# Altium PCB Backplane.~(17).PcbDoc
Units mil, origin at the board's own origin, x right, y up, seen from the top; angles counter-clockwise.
Board outline 6520 x 1500 mil, 6 copper layers (Top Layer, DGND, +5V, AGND, VCC, Bottom Layer), stack 50.76 mil thick; 22 components, 84 nets, 235 pads, 4 vias.
Unrouted connection lines stored in the file: 38.
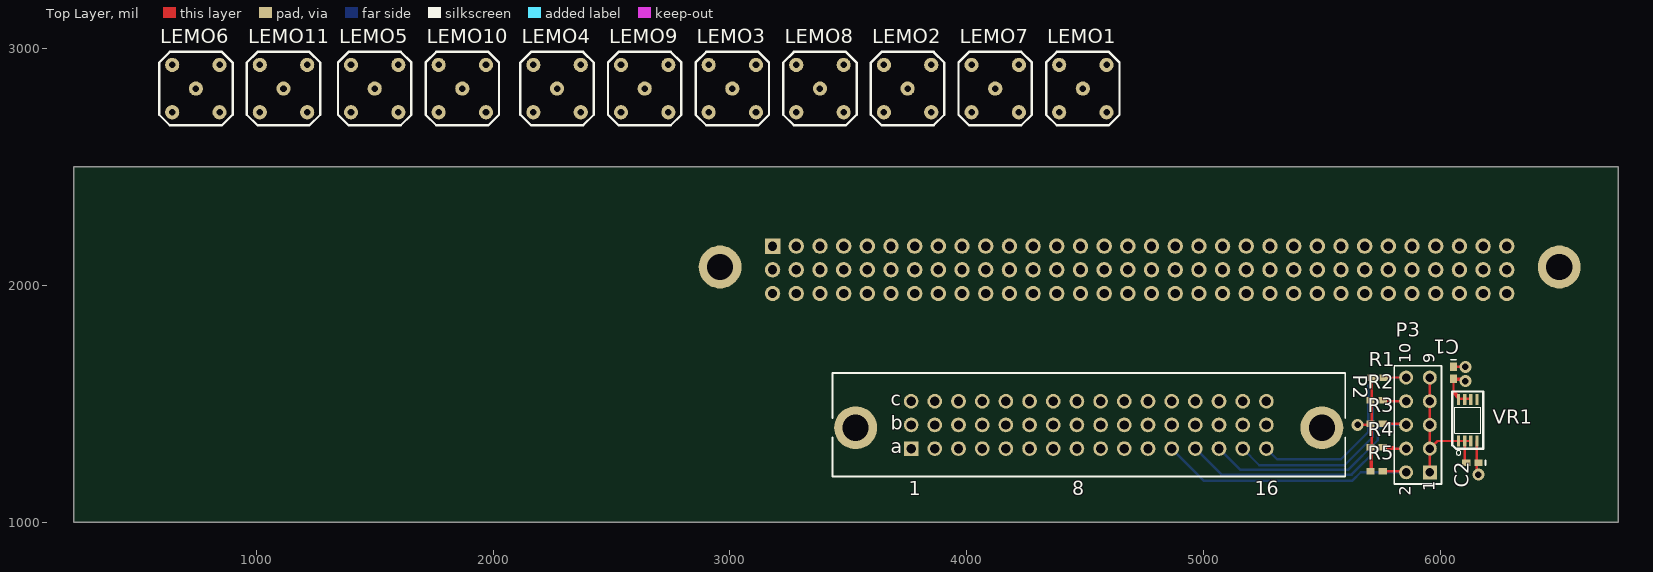
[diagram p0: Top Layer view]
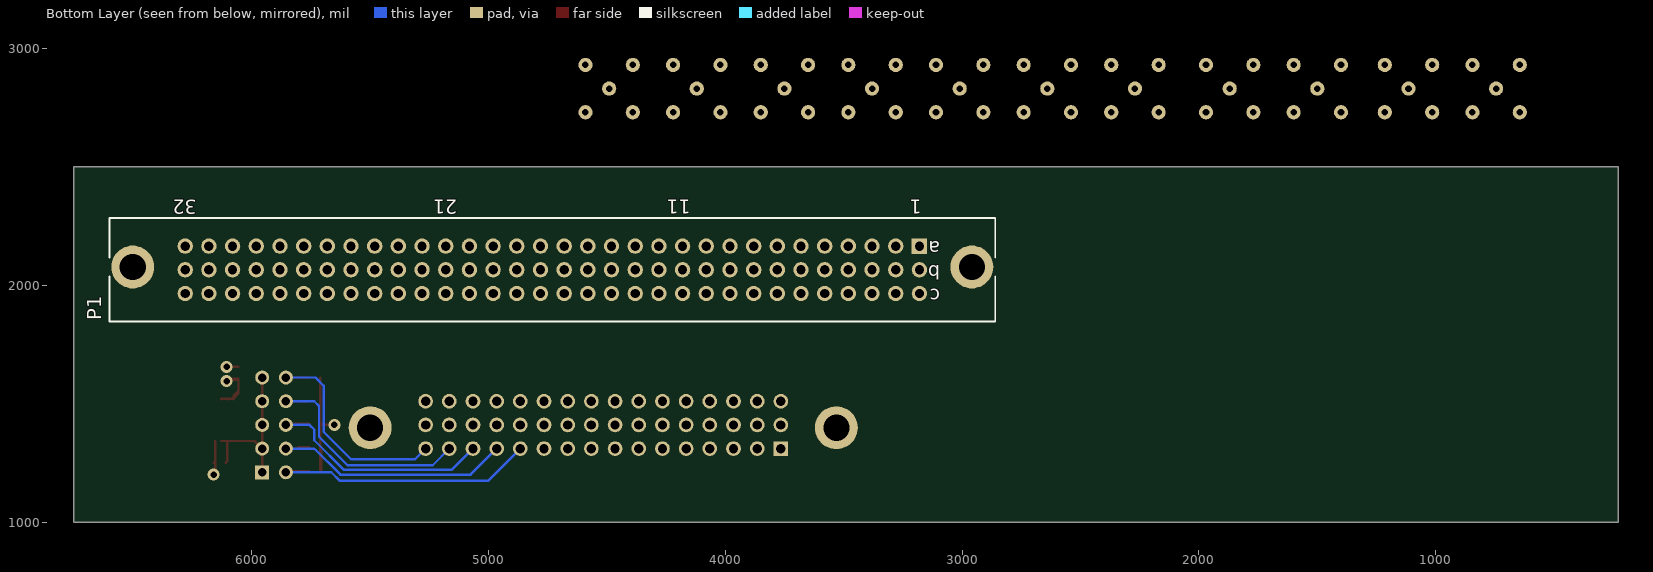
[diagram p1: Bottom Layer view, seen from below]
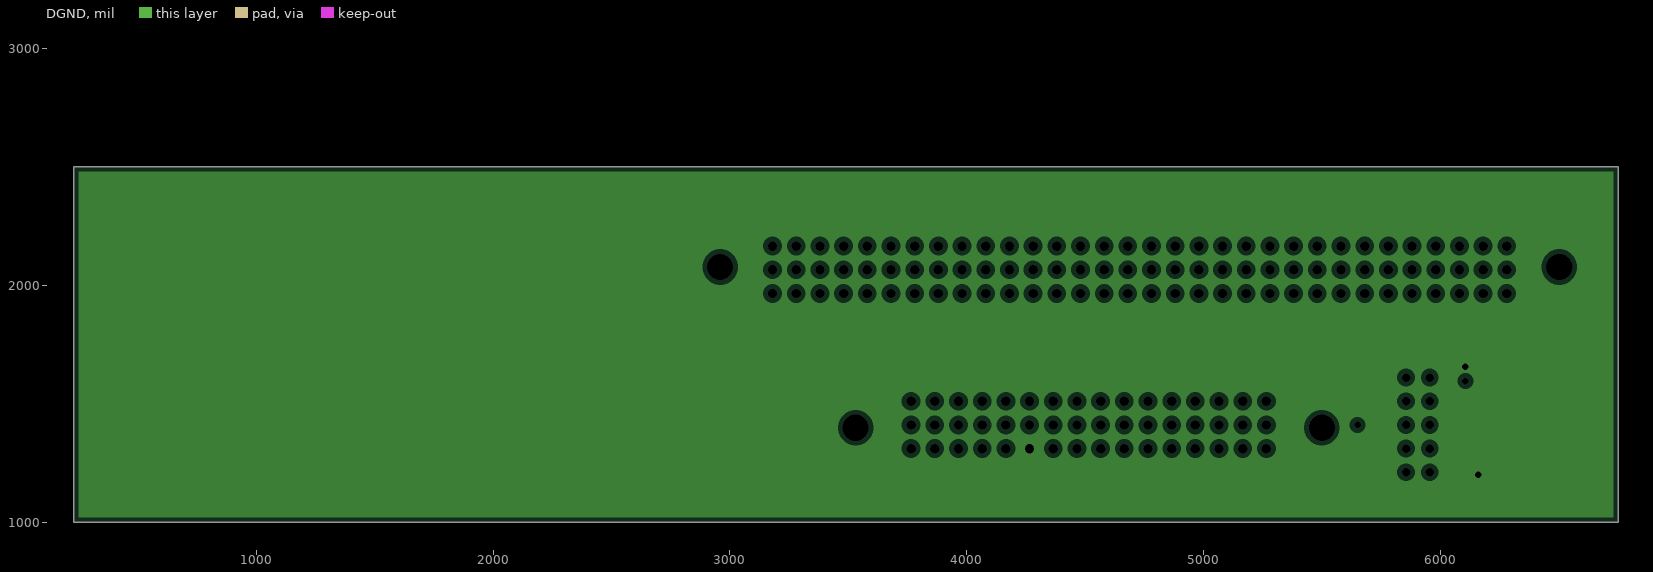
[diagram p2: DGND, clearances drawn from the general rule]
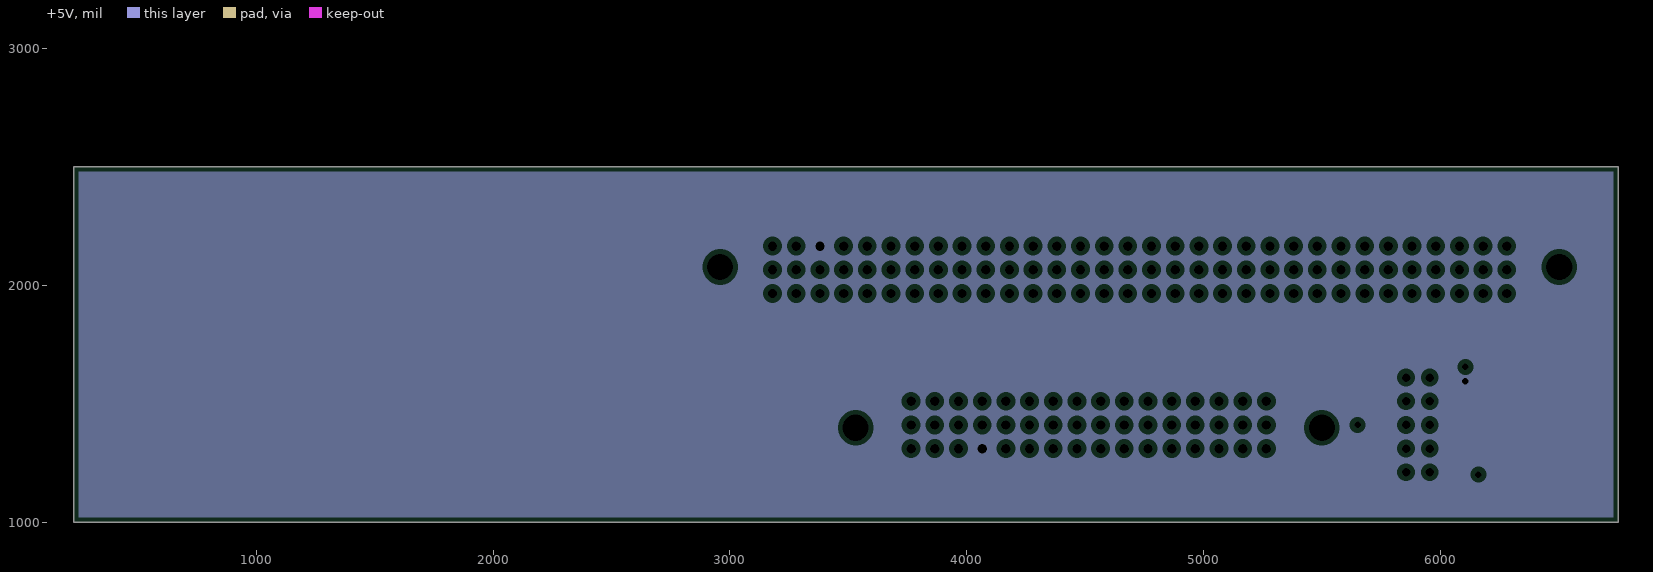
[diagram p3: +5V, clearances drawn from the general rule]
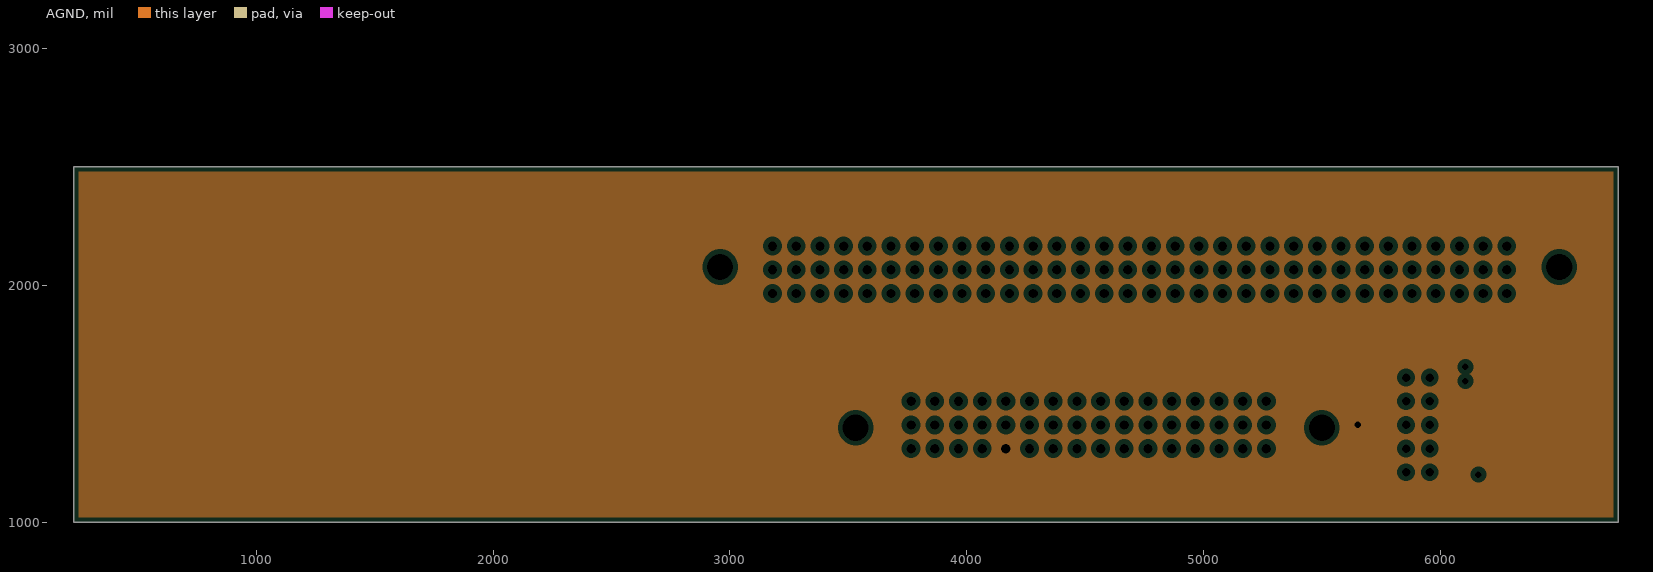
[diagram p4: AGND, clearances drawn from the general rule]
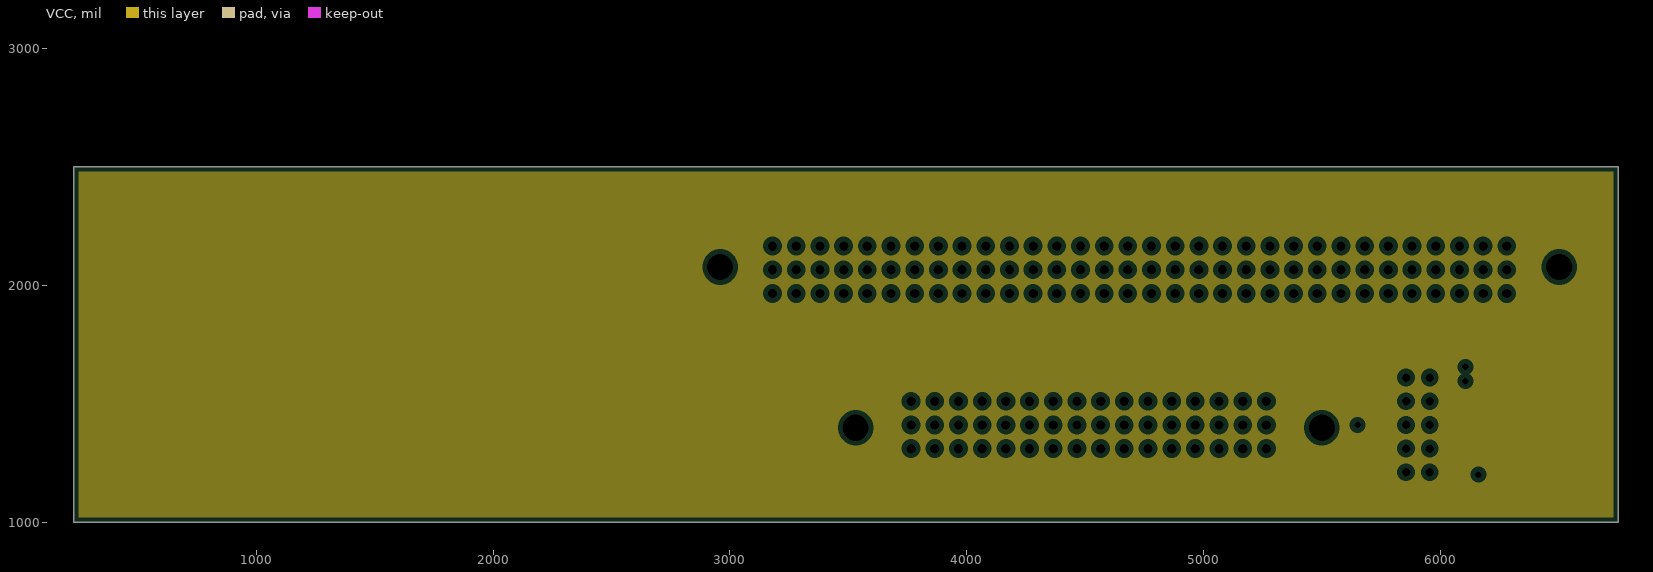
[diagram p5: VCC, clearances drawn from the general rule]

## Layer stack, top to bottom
Top Layer: signal copper 1.4
Dielectric: prepreg 5.1, FR-4, Dk 4.8
DGND: plane copper 1.4, net DGND
Dielectric: core 10.72, FR-4, Dk 4.8
+5V: plane copper 1.4, net +5V
Dielectric: prepreg 10.72, FR-4, Dk 4.8
AGND: plane copper 1.4, net AGND
Dielectric: core 10.72, FR-4, Dk 4.8
VCC: plane copper 1.4
Dielectric: prepreg 5.1, FR-4, Dk 4.8
Bottom Layer: signal copper 1.4

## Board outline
230,1000 6750,1000 6750,2500 230,2500

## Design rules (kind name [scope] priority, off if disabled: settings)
Clearance [All] p1: gap=10
ComponentClearance [All] p1: gap=10 collisioncheckmode=3 verticalgap=10
PlaneClearance [All] p1: clearance=20
PlaneConnect [All] p1: planeconnectstyle=Relief reliefexpansion=20 reliefentries=4 reliefconductorwidth=10 reliefairgap=10
PolygonConnect [All] p1: connectstyle=Relief reliefconductorwidth=10 reliefentries=4 polygonreliefangle="90 Angle"
RoomDefinition LEMO [InComponentClass('LEMO')] p1: confinementstyle=ConfineIn formatcopy=TRUE lockcomponents=FALSE outline 580,2665 4655,2665 4655,3100 580,3100
RoomDefinition "Digital Connector" [InComponentClass('Digital Connector')] p2: confinementstyle=ConfineIn formatcopy=TRUE lockcomponents=FALSE outline 3170,1085 6595,1085 6595,1895 3170,1895
RoomDefinition "Analog Connector" [InComponentClass('Analog Connector')] p3: confinementstyle=ConfineIn formatcopy=TRUE lockcomponents=FALSE outline 2650,1745 6670,1745 6670,2420 2650,2420
RoutingVias [All] p1: holewidth=28 width=50 viastyle="Through Hole" minholewidth=28 minwidth=50 maxholewidth=28 maxwidth=50
SolderMaskExpansion [All] p1: expansion=4
SupplyNets VCC [OnLayer('VCC')] p1: voltage=10.00
SupplyNets +5V [OnLayer('+5V')] p2: voltage=5.000
SupplyNets DGND [OnLayer(DGND)] p3: voltage=0.000
SupplyNets AGND [OnLayer('AGND')] p4: voltage=0.000
TestPointUsage [All] p1: valid=0 allowmultiple=FALSE
Testpoint [All] p1: side=15 testpointundercomponent=TRUE minsize=40 maxsize=100 preferedsize=60 minholesize=0 maxholesize=40 preferedholesize=32 testpointgrid=1 style=1023 order=0123456789
Width Width_BIAS [InNetClass('BIAS')] p1: maxlimit=10 minlimit=4 preferedwidth=5
Width [All] p2: maxlimit=7.35 minlimit=2.1 preferedwidth=7.35 impedancedriven=TRUE minimp=50.000000 maximp=80.000000 favimp=50.000000
16 further rules are at their usual default settings.

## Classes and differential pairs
net class BIAS: SIPMBIAS1 SIPMBIAS2 SIPMBIAS3 SIPMBIAS4 SIPMBIAS5 SIPMBIAS6 SIPMBIAS7 SIPMBIAS8 SIPMBIAS9 SIPMBIAS10 SIPMBIAS11 SIPMBIAS12 SIPMBIAS13 SIPMBIAS14 SIPMBIAS15 SIPMBIAS16 SIPMBIAS17 SIPMBIAS18 SIPMBIAS19 SIPMBIAS20 SIPMBIAS21 SIPMBIAS22 SIPMBIAS23 SIPMBIAS24 SIPMBIAS25 SIPMBIAS26 SIPMBIAS27 SIPMBIAS28 SIPMBIAS29 SIPMBIAS30 SIPMBIAS31 SIPMBIAS32
component class LEMO: LEMO1 LEMO2 LEMO3 LEMO4 LEMO5 LEMO6 LEMO7 LEMO8 LEMO9 LEMO10 LEMO11
component class "Digital Connector": C1 C2 P2 P3 R1 R2 R3 R4 R5 R? VR1
component class "Analog Connector": P1

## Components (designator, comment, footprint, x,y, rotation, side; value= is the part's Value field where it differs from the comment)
C1 "Kemet C0402C104K8PACTU" 0402 6055,1630 r270 top
C2 "Kemet C1206C106K9PACTU" 0402 6135,1250 r180 top
LEMO1 "LEMO EPA.00" "LEMO EPA.00" 4490,2830 r0 top
LEMO2 "LEMO EPA.00" "LEMO EPA.00" 3750,2830 r0 top
LEMO3 "LEMO EPA.00" "LEMO EPA.00" 3010,2830 r0 top
LEMO4 "LEMO EPA.00" "LEMO EPA.00" 2270,2830 r0 top
LEMO5 "LEMO EPA.00" "LEMO EPA.00" 1500,2830 r0 top
LEMO6 "LEMO EPA.00" "LEMO EPA.00" 745,2830 r0 top
LEMO7 "LEMO EPA.00" "LEMO EPA.00" 4120,2830 r0 top
LEMO8 "LEMO EPA.00" "LEMO EPA.00" 3380,2830 r0 top
LEMO9 "LEMO EPA.00" "LEMO EPA.00" 2640,2830 r0 top
LEMO10 "LEMO EPA.00" "LEMO EPA.00" 1870,2830 r0 top
LEMO11 "LEMO EPA.00" "LEMO EPA.00" 1115,2830 r0 top
P1 "DIN41612 96 pin, Backplane" EURO2.54-2V96 4730,2065 r0 bottom
P2 "DIN41612 48 pin, Backplane" EURO2.54-2V48 4515,1410 r0 top
P3 "Header 5X2" HDR2X5 5955,1210 r90 top
R1 "Res2" 1005[0402] 5735,1610 r0 top
R2 "Res2" 1005[0402] 5730,1515 r0 top
R3 "Res2" 1005[0402] 5730,1415 r0 top
R4 "Res2" 1005[0402] 5730,1315 r0 top
R5 "Res2" 1005[0402] 5730,1215 r0 top
VR1 "" RM-8 6115,1430 r0 top

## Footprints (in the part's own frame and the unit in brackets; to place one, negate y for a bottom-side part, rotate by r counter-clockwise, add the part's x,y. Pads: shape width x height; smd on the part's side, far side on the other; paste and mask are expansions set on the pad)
0402 [mm] "Chip Capacitor; Body 1.0 x 0.5 mm (LxW typ)"
  rect 0.9x0.7 smd: 1(-0.65,0) 2(0.65,0)
  silkscreen extent -1.4,-0.25 -1.4,0.25
1005[0402] [mm] "Chip Resistor; Body 1.1 x 0.5 mm (LxW typ)"
  rect 0.9x0.7 smd: 1(-0.65,0) 2(0.65,0)
EURO2.54-2V48 [mil] "Connector; DIN 41612, Type 2C, Thru-Hole; Rows a+b+c, 48 Position; Vertical"
  round 181.1 hole 110.24: 17(-984.25,-11.81) 18(984.25,-11.81)
  rect 62x62 hole 39.37: A1(-750,-100)
  round 62 hole 39.37: A2(-650,-100) A3(-550,-100) A4(-450,-100) A5(-350,-100) A6(-250,-100) A7(-150,-100) A8(-50,-100) A9(50,-100) A10(150,-100) A11(250,-100) A12(350,-100) A13(450,-100) A14(550,-100) A15(650,-100) A16(750,-100) B1(-750,0) B2(-650,0) B3(-550,0) B4(-450,0) B5(-350,0) B6(-250,0) B7(-150,0) B8(-50,0) B9(50,0) B10(150,0) B11(250,0) B12(350,0) B13(450,0) B14(550,0) B15(650,0) B16(750,0) C1(-750,100) C2(-650,100) C3(-550,100) C4(-450,100) C5(-350,100) C6(-250,100) C7(-150,100) C8(-50,100) C9(50,100) C10(150,100) C11(250,100) C12(350,100) C13(450,100) C14(550,100) C15(650,100) C16(750,100)
  silkscreen extent -1083,-219 1083,219
EURO2.54-2V96 [mm] "Connector; DIN 41612, Type C, Thru-Hole; Rows a+b+c, 96 Position; Vertical"
  round 4.6 hole 2.8: 33(-45,-0.3) 34(45,-0.3)
  rect 1.65x1.65 hole 1: A1(-39.37,-2.54)
  round 1.65 hole 1: A2(-36.83,-2.54) A3(-34.29,-2.54) A4(-31.75,-2.54) A5(-29.21,-2.54) A6(-26.67,-2.54) A7(-24.13,-2.54) A8(-21.59,-2.54) A9(-19.05,-2.54) A10(-16.51,-2.54) A11(-13.97,-2.54) A12(-11.43,-2.54) A13(-8.89,-2.54) A14(-6.35,-2.54) A15(-3.81,-2.54) A16(-1.27,-2.54) A17(1.27,-2.54) A18(3.81,-2.54) A19(6.35,-2.54) A20(8.89,-2.54) A21(11.43,-2.54) A22(13.97,-2.54) A23(16.51,-2.54) A24(19.05,-2.54) A25(21.59,-2.54) A26(24.13,-2.54) A27(26.67,-2.54) A28(29.21,-2.54) A29(31.75,-2.54) A30(34.29,-2.54) A31(36.83,-2.54) A32(39.37,-2.54) B1(-39.37,0) B2(-36.83,0) B3(-34.29,0) B4(-31.75,0) B5(-29.21,0) B6(-26.67,0) B7(-24.13,0) B8(-21.59,0) B9(-19.05,0) B10(-16.51,0) B11(-13.97,0) B12(-11.43,0) B13(-8.89,0) B14(-6.35,0) B15(-3.81,0) B16(-1.27,0) B17(1.27,0) B18(3.81,0) B19(6.35,0) B20(8.89,0) B21(11.43,0) B22(13.97,0) B23(16.51,0) B24(19.05,0) B25(21.59,0) B26(24.13,0) B27(26.67,0) B28(29.21,0) B29(31.75,0) B30(34.29,0) B31(36.83,0) B32(39.37,0) C1(-39.37,2.54) C2(-36.83,2.54) C3(-34.29,2.54) C4(-31.75,2.54) C5(-29.21,2.54) C6(-26.67,2.54) C7(-24.13,2.54) C8(-21.59,2.54) C9(-19.05,2.54) C10(-16.51,2.54) C11(-13.97,2.54) C12(-11.43,2.54) C13(-8.89,2.54) C14(-6.35,2.54) C15(-3.81,2.54) C16(-1.27,2.54) C17(1.27,2.54) C18(3.81,2.54) C19(6.35,2.54) C20(8.89,2.54) C21(11.43,2.54) C22(13.97,2.54) C23(16.51,2.54) C24(19.05,2.54) C25(21.59,2.54) C26(24.13,2.54) C27(26.67,2.54) C28(29.21,2.54) C29(31.75,2.54) C30(34.29,2.54) C31(36.83,2.54) C32(39.37,2.54)
  silkscreen extent -47.5,-5.55 47.5,5.55
HDR2X5 [mm] "Connector; Header; 5x2 Position"
  rect 1.5x1.5 hole 0.9: 1(0,0)
  round 1.5 hole 0.9: 2(0,2.54) 3(2.54,0) 4(2.54,2.54) 5(5.08,0) 6(5.08,2.54) 7(7.62,0) 8(7.62,2.54) 9(10.16,0) 10(10.16,2.54)
  silkscreen extent -1.27,-1.27 11.43,3.81
"LEMO EPA.00" [mil]
  round 60 hole 27.56: 0(0,0) 1(-100,100) 2(100,100) 3(100,-100) 4(-100,-100)
  silkscreen extent -155,-155 155,155
RM-8 [mil]
  rect 13.4x46.9 smd: 1(-38.6,-87.8) 2(-12.6,-87.8) 3(12.6,-87.8) 4(38.6,-87.8) 5(38.6,87.8) 6(12.6,87.8) 7(-12.6,87.8) 8(-38.6,87.8)
  silkscreen extent -65,-148 65,121

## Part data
C1 C2: library part Cap, "Capacitor"
P3: "Header, 5-Pin, Dual row"
R1 R2 R3 R4 R5: "Resistor"
VR1: library part ADP3335

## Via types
v1: diameter 50, hole 28, Top Layer to Bottom Layer, 4 vias

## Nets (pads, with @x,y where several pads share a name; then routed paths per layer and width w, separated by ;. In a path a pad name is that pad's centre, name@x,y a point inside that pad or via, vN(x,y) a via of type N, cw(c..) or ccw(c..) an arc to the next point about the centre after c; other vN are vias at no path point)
+3.3V: C2.2 P3.1 P3.3 P3.5 P3.7 P3.9 VR1.1 VR1.2 VR1.3 | length 681
  Top Layer w10: P3.1 P3.3 ; P3.9 P3.7 P3.5 P3.3 ; C2.2 6102.4,1257.01 VR1.2 ; VR1.3 VR1.2 ; P3.3 5987.2,1342.2 VR1.1 VR1.2
+5V: C1.2 P1.A3 P2.A4 VR1.6 VR1.7 VR1.8 | length 470.4
  Top Layer w10: VR1.8 VR1.8@6076.4,1521 ; VR1.7 VR1.7@6102.4,1520 ; v1(6105,1595) v1@6100,1600 ; VR1.6 VR1.6@6127.6,1520 ; 6055,1554.4 C1.2@6055,1600 ; 6055,1554.4 6055,1543.6 VR1.8@6076.4,1522.2 ; 6055,1554.4 6076.4,1533 VR1.8@6076.4,1522.2 ; C1.2@6055,1600 v1@6100,1600 ; C1.2@6055,1600 C1.2 6095.59,1604.41 v1@6100,1600 ; C1.2@6055,1600 v1@6100,1600 ; VR1.8@6076.4,1521 VR1.8@6077.6,1521 ; VR1.8@6076.4,1521 VR1.8@6076.4,1522.2 ; VR1.8@6076.4,1521 VR1.8@6077.6,1521 ; VR1.8@6076.4,1522.2 VR1.8@6077.6,1521 ; VR1.8@6077.6,1521 VR1.8@6078.6,1520 ; VR1.8@6077.6,1521 VR1.7@6102.4,1521 ; VR1.8@6077.6,1521 VR1.7@6102.4,1521 ; VR1.8@6077.6,1521 VR1.8@6078.6,1520 ; VR1.8@6078.6,1520 VR1.7@6102.4,1520 ; VR1.8@6078.6,1520 VR1.7@6102.4,1520 ; v1@6100,1600 v1@6105,1600 ; v1@6100,1600 v1@6105,1600 ; VR1.7@6102.4,1520 VR1.6@6127.6,1520 ; VR1.7@6102.4,1520 VR1.7@6102.4,1521 ; VR1.7@6102.4,1520 VR1.6@6127.6,1520 ; v1@6105,1600 6115,1600 v1@6105,1600
+210V: P2.A2
-5V: P2.A3
ADC_EXT1: P2.A7
ADC_EXT2: P2.A8
AGND: LEMO1.1 LEMO1.2 LEMO1.3 LEMO1.4 LEMO2.1 LEMO2.2 LEMO2.3 LEMO2.4 LEMO3.1 LEMO3.2 LEMO3.3 LEMO3.4 LEMO4.1 LEMO4.2 LEMO4.3 LEMO4.4 LEMO5.1 LEMO5.2 LEMO5.3 LEMO5.4 LEMO6.1 LEMO6.2 LEMO6.3 LEMO6.4 LEMO7.1 LEMO7.2 LEMO7.3 LEMO7.4 LEMO8.1 LEMO8.2 LEMO8.3 LEMO8.4 LEMO9.1 LEMO9.2 LEMO9.3 LEMO9.4 LEMO10.1 LEMO10.2 LEMO10.3 LEMO10.4 LEMO11.1 LEMO11.2 LEMO11.3 LEMO11.4 P2.A5 R1.1 R2.1 R3.1 R4.1 R5.1 | length 1259.6
  Top Layer w10: v1(5650,1410) R3.1@5699.41,1410 ; R5.1 R5.1@5705,1215 ; R4.1 R4.1@5705,1315 ; R2.1 R2.1@5709,1515 ; R3.1@5699.41,1410 R3.1@5699.41,1415 ; R3.1@5699.41,1410 R3.1@5699.41,1415 ; R3.1@5699.41,1415 R3.1 R3.1@5709,1415 ; R5.1@5705,1215 R4.1@5705,1315 ; R5.1@5705,1215 R4.1@5705,1315 ; R4.1@5705,1315 R4.1@5709.41,1315 ; R3.1@5709,1415 R2.1@5709,1515 ; R3.1@5709,1415 R2.1@5709,1515 ; R2.1@5709,1515 R2.1@5709.41,1515 ; R4.1@5709.41,1315 5709.41,1220 R4.1@5709.41,1315 ; R4.1@5709.41,1315 R3.1@5709.41,1415 ; R4.1@5709.41,1315 R3.1@5709.41,1415 ; R3.1@5709.41,1415 R2.1@5709.41,1515 ; R3.1@5709.41,1415 R2.1@5709.41,1515 ; R2.1@5709.41,1515 R1.1 R2.1@5709.41,1515
CP2201/LA: P2.A1
DGND: C1.1 C2.1 P2.A6 VR1.4 | length 337.9
  Top Layer w10: C1.1 6104.41,1655.59 v1(6105,1655) ; v1(6160,1200) v1@6153.6,1206.4 ; C2.1 C2.1@6153.6,1250 ; v1@6153.6,1206.4 C2.1@6153.6,1250 ; v1@6153.6,1206.4 C2.1@6153.6,1250 ; C2.1@6153.6,1250 VR1.4 C2.1@6153.6,1250
ID0: P2.A16 P3.10 R1.2 | length 960.2
  Top Layer w10: R1.2 P3.10
  Bottom Layer w10: P2.A16 5310,1265 5580,1265 5695,1380 5695,1575 5730,1610 P3.10
ID1: P2.A15 P3.8 R2.2 | length 1001.4
  Top Layer w10: R2.2@5760.59,1510 P3.8
  Bottom Layer w10: P2.A15 5235,1240 5595,1240 5715,1360 5715,1490 5735,1510 P3.8
ID2: P2.A14 P3.6 R3.2 | length 1136.2
  Top Layer w10: P3.6 P3.6@5855,1415 ; P3.6@5855,1415 R3.2 P3.6@5855,1415
  Bottom Layer w10: P2.A14 5155,1220 5610,1220 5735,1345 5735,1390 5755,1410 P3.6
ID3: P2.A13 P3.4 R4.2 | length 1129
  Top Layer w10: R4.2 5802,1315 5807,1310 ; R4.2@5760.59,1310 5807,1310 ; P3.4 5807,1310
  Bottom Layer w10: P2.A13 5075,1200 5625,1200 5735,1310 P3.4
ID4: P2.A12 P3.2 R5.2 | length 1264.2
  Top Layer w10: P3.2 P3.2@5855,1215 ; P3.2@5855,1215 R5.2 P3.2@5855,1215
  Bottom Layer w10: P2.A12 5000,1175 5628.28,1175 5663.28,1210 P3.2
SIPMBIAS1: P1.B1 P2.C1
SIPMBIAS2: P1.B2 P2.B1
SIPMBIAS3: P1.B3 P2.C2
SIPMBIAS4: P1.B4 P2.B2
SIPMBIAS5: P1.B5 P2.C3
SIPMBIAS6: P1.B6 P2.B3
SIPMBIAS7: P1.B7 P2.C4
SIPMBIAS8: P1.B8 P2.B4
SIPMBIAS9: P1.B9 P2.C5
SIPMBIAS10: P1.B10 P2.B5
SIPMBIAS11: P1.B11 P2.C6
SIPMBIAS12: P1.B12 P2.B6
SIPMBIAS13: P1.B13 P2.C7
SIPMBIAS14: P1.B14 P2.B7
SIPMBIAS15: P1.B15 P2.C8
SIPMBIAS16: P1.B16 P2.B8
SIPMBIAS17: P1.B17 P2.C9
SIPMBIAS18: P1.B18 P2.B9
SIPMBIAS19: P1.B19 P2.C10
SIPMBIAS20: P1.B20 P2.B10
SIPMBIAS21: P1.B21 P2.C11
SIPMBIAS22: P1.B22 P2.B11
SIPMBIAS23: P1.B23 P2.C12
SIPMBIAS24: P1.B24 P2.B12
SIPMBIAS25: P1.B25 P2.C13
SIPMBIAS26: P1.B26 P2.B13
SIPMBIAS27: P1.B27 P2.C14
SIPMBIAS28: P1.B28 P2.B14
SIPMBIAS29: P1.B29 P2.C15
SIPMBIAS30: P1.B30 P2.B15
SIPMBIAS31: P1.B31 P2.C16
SIPMBIAS32: P1.B32 P2.B16
SIPMOUT1: P1.C1
SIPMOUT2: P1.C2
SIPMOUT3: P1.C3
SIPMOUT4: P1.C4
SIPMOUT5: P1.C5
SIPMOUT6: P1.C6
SIPMOUT7: P1.C7
SIPMOUT8: P1.C8
SIPMOUT9: P1.C9
SIPMOUT10: P1.C10
SIPMOUT11: P1.C11
SIPMOUT12: P1.C12
SIPMOUT13: P1.C13
SIPMOUT14: P1.C14
SIPMOUT15: P1.C15
SIPMOUT16: P1.C16
SIPMOUT17: P1.C17
SIPMOUT18: P1.C18
SIPMOUT19: P1.C19
SIPMOUT20: P1.C20
SIPMOUT21: P1.C21
SIPMOUT22: P1.C22
SIPMOUT23: P1.C23
SIPMOUT24: P1.C24
SIPMOUT25: P1.C25
SIPMOUT26: P1.C26
SIPMOUT27: P1.C27
SIPMOUT28: P1.C28
SIPMOUT29: P1.C29
SIPMOUT30: P1.C30
SIPMOUT31: P1.C31
SIPMOUT32: P1.C32
SUMMED1: LEMO1.0 LEMO6.0 P1.A1
SUMMED2: LEMO2.0 P1.A6
SUMMED3: LEMO3.0 P1.A11
SUMMED4: LEMO4.0 P1.A16
SUMMED5: LEMO5.0 P1.A21
SUMMED6: P1.A26
pads on no net: LEMO7.0 LEMO8.0 LEMO9.0 LEMO10.0 LEMO11.0 P1.33 P1.34 P1.A2 P1.A4 P1.A5 P1.A7 P1.A8 P1.A9 P1.A10 P1.A12 P1.A13 P1.A14 P1.A15 P1.A17 P1.A18 P1.A19 P1.A20 P1.A22 P1.A23 P1.A24 P1.A25 P1.A27 P1.A28 P1.A29 P1.A30 P1.A31 P1.A32 P2.17 P2.18 P2.A9 P2.A10 P2.A11 VR1.5

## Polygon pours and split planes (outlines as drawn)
DGND on DGND (split plane): 6729.61,1020.39 250.39,1020.39 250.39,2479.61 6729.61,2479.61
AGND on AGND (split plane): 6729.61,1020.39 250.39,1020.39 250.39,2479.61 6729.61,2479.61
+5V on +5V (split plane): 6729.61,1020.39 250.39,1020.39 250.39,2479.61 6729.61,2479.61
no net on VCC (split plane): 6729.61,1020.39 250.39,1020.39 250.39,2479.61 6729.61,2479.61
